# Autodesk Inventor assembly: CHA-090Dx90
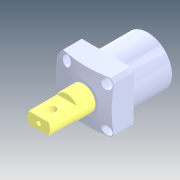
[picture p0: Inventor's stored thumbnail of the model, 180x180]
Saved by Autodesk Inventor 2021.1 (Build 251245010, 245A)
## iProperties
Created: 2018-07
Part Number: CHA-090Dx90
Description: STEP AP214
Document SubType Name: Assembly
Designer: user
Title: CHA-090Dx90.STEP
Revision Number: ÈÎºÎ
Sending System: SolidWorks 2016
Preprocessor: SwSTEP 2.0
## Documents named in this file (3)
- D:\Vault_2016\Projekty\Clamptek\Hydraulic\CHA\CHA\CHA-090\Inventor\CHA-090Dx90\CHA-090Dx90.iam
- D:\Vault_2016\Projekty\Clamptek\Hydraulic\CHA\CHA\CHA-090\Inventor\CHA-090Dx90\CHA-090±¾Ìå.ipt
- D:\Vault_2016\Projekty\Clamptek\Hydraulic\CHA\CHA\CHA-090\Inventor\CHA-090Dx90\CHA-090D»îÈû¸Ë.ipt
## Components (2 placed, 2 different names)
1. CHA-090±¾Ìå_1
2. CHA-090D»îÈû¸Ë_2
